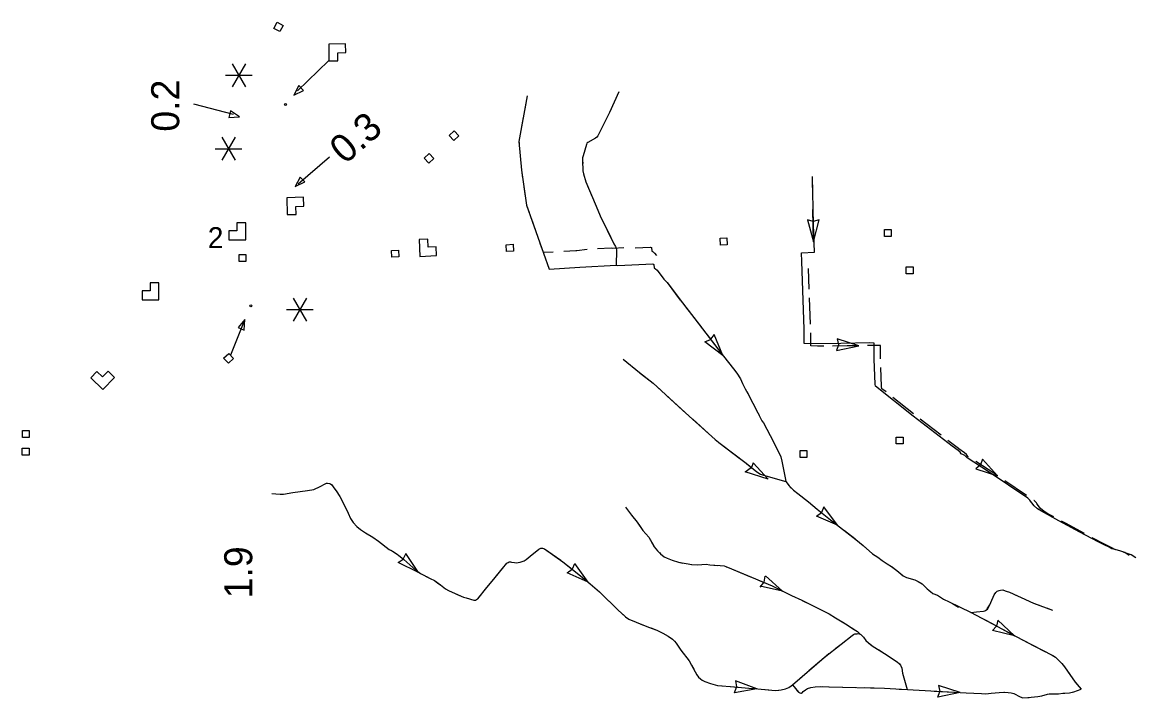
# Model space of a CAD drawing. Extents: x -160 to 6143532, y -375 to 762199.
# Drawn here: x -140.26 to -105.52, y -293.96 to -272.89 of the extents above; entities that cross this region are included whole.
import ezdxf

# ---------------------------------------------------------------- set-up
doc = ezdxf.new("R2010")
doc.units = 0
for name, color, linetype in [('Level 43', 7, 'Continuous'), ('Level 48', 7, 'Continuous'), ('Level 56', 7, 'Continuous'), ('Level 57', 7, 'Continuous'), ('Level 58', 7, 'Continuous')]:
    doc.layers.add(name, color=color, linetype=linetype)

msp = doc.modelspace()

# ---------------------------------------------------------------- linework, layer by layer
at = {"layer": 'Level 43'}
for p, q in [((-115.582, -279.105), (-115.766, -279.059)), ((-115.766, -279.059), (-115.572, -279.742)), ((-115.398, -279.053), (-115.58, -279.105)), ((-115.572, -279.742), (-115.398, -279.053)), ((-118.669, -282.632), (-118.785, -282.781)), ((-118.4, -283.288), (-118.669, -282.632)), ((-114.158, -282.98), (-114.834, -282.763)), ((-114.834, -282.763), (-114.794, -282.948)), ((-118.962, -282.854), (-118.787, -282.783)), ((-118.4, -283.288), (-118.962, -282.854)), ((-114.794, -282.95), (-114.852, -283.13)), ((-114.852, -283.13), (-114.158, -282.98)), ((-110.305, -286.514), (-110.364, -286.694)), ((-109.83, -287.042), (-110.305, -286.514)), ((-117.701, -286.915), (-117.515, -286.777)), ((-116.991, -287.138), (-117.701, -286.915)), ((-117.452, -286.635), (-117.513, -286.775)), ((-116.991, -287.138), (-117.452, -286.635)), ((-110.365, -286.696), (-110.505, -286.823)), ((-110.505, -286.823), (-109.83, -287.042)), ((-115.476, -288.298), (-115.325, -288.184)), ((-114.823, -288.576), (-115.476, -288.298)), ((-115.249, -288.008), (-115.323, -288.182)), ((-114.823, -288.576), (-115.249, -288.008)), ((-128.53, -289.742), (-128.377, -289.632)), ((-128.298, -289.458), (-128.375, -289.63)), ((-127.896, -290.05), (-128.291, -289.46)), ((-127.896, -290.05), (-128.533, -289.737)), ((-123.255, -290.065), (-123.103, -289.953)), ((-122.608, -290.352), (-123.255, -290.06)), ((-123.027, -289.777), (-123.102, -289.951)), ((-122.608, -290.352), (-123.022, -289.776)), ((-117.235, -290.51), (-117.12, -290.361)), ((-117.093, -290.171), (-117.119, -290.358)), ((-116.543, -290.629), (-117.071, -290.155)), ((-116.543, -290.629), (-117.238, -290.483)), ((-109.993, -291.862), (-109.864, -291.724)), ((-109.82, -291.537), (-109.863, -291.721)), ((-109.302, -292.022), (-109.82, -291.537)), ((-109.302, -292.022), (-109.993, -291.862)), ((-117.338, -293.679), (-118.004, -293.435)), ((-118.004, -293.435), (-117.972, -293.621)), ((-118.037, -293.801), (-117.972, -293.623)), ((-117.338, -293.679), (-118.037, -293.801)), ((-111.691, -293.94), (-111.632, -293.761)), ((-110.996, -293.795), (-111.691, -293.94)), ((-110.996, -293.795), (-111.671, -293.573)), ((-111.671, -293.573), (-111.632, -293.758))]:
    msp.add_line(p, q, dxfattribs=at)
for points in [[(-121.644, -275.063), (-121.934, -275.707), (-122.236, -276.309), (-122.302, -276.435), (-122.337, -276.477), (-122.38, -276.511), (-122.614, -276.645), (-122.642, -276.667), (-122.659, -276.708), (-122.765, -277.061), (-122.782, -277.121), (-122.778, -277.206), (-122.767, -277.528), (-122.746, -277.622), (-122.676, -277.87), (-122.354, -278.63), (-122.227, -278.933), (-121.803, -279.799), (-121.747, -279.884), (-121.732, -279.936), (-121.723, -280.005), (-121.728, -280.466)], [(-124.503, -275.192), (-124.767, -276.611), (-124.685, -277.508), (-124.525, -278.599), (-123.824, -280.59), (-122.869, -280.529), (-121.728, -280.466), (-121.675, -280.475), (-120.586, -280.432), (-120.557, -280.447), (-120.541, -280.562), (-120.499, -280.582), (-120.454, -280.623), (-120.243, -280.907), (-120.142, -281.014), (-119.665, -281.644), (-119.379, -282.005), (-118.385, -283.308), (-118.065, -283.699), (-117.963, -283.841), (-117.854, -284.016), (-117.791, -284.155), (-117.71, -284.322), (-117.627, -284.47), (-117.308, -285.075), (-117.181, -285.325), (-117.131, -285.383), (-116.928, -285.777), (-116.638, -286.35), (-116.595, -286.448), (-116.567, -286.583), (-116.468, -287.049), (-116.435, -287.219), (-116.334, -287.353), (-116.194, -287.488), (-116.064, -287.588), (-115.725, -287.847), (-115.458, -288.078), (-115.04, -288.406), (-114.253, -289.019), (-114.024, -289.213), (-113.73, -289.466), (-113.566, -289.574), (-113.436, -289.681), (-113.28, -289.781), (-113.144, -289.862), (-112.976, -289.985), (-112.775, -290.151), (-112.672, -290.204), (-112.416, -290.281), (-112.307, -290.33), (-112.185, -290.403), (-112.025, -290.557), (-111.925, -290.648), (-111.848, -290.703), (-111.702, -290.761), (-111.514, -290.879), (-111.343, -290.964), (-110.68, -291.293), (-110.321, -291.479), (-109.058, -292.152), (-108.126, -292.631), (-108.025, -292.692), (-107.936, -292.773), (-107.828, -292.885), (-107.739, -292.994), (-107.405, -293.472), (-107.228, -293.687)], [(-124.503, -275.192), (-124.578, -275.594)], [(-121.924, -275.685), (-121.934, -275.707), (-122.236, -276.309), (-122.292, -276.417)], [(-124.628, -275.863), (-124.767, -276.611), (-124.762, -276.669)], [(-122.504, -276.582), (-122.614, -276.645), (-122.642, -276.667), (-122.659, -276.708), (-122.765, -277.061), (-122.782, -277.121), (-122.778, -277.206), (-122.775, -277.302)], [(-124.737, -276.941), (-124.685, -277.508), (-124.649, -277.755)], [(-122.757, -277.574), (-122.746, -277.622), (-122.676, -277.87), (-122.477, -278.342)], [(-105.721, -289.521), (-105.865, -289.428), (-106.017, -289.377), (-106.208, -289.323), (-106.266, -289.31), (-106.348, -289.266), (-106.485, -289.196), (-106.692, -289.094), (-107.262, -288.791), (-107.917, -288.441), (-108.464, -288.142), (-108.582, -288.069), (-108.69, -287.977), (-108.767, -287.881), (-108.805, -287.827), (-108.821, -287.798), (-108.887, -287.735), (-110.122, -286.904), (-110.778, -286.474), (-110.851, -286.407), (-110.889, -286.388), (-110.962, -286.356), (-110.997, -286.299), (-111.064, -286.245), (-111.245, -286.117), (-112.464, -285.178), (-113.638, -284.245), (-113.651, -284.175), (-113.679, -283.395), (-113.686, -282.896), (-113.816, -282.892), (-114.726, -282.912), (-115.652, -282.921), (-115.862, -282.908), (-115.862, -282.459), (-115.938, -280.358), (-115.944, -280.08), (-115.543, -280.058), (-115.569, -279.198), (-115.61, -277.699)], [(-115.591, -278.408), (-115.61, -277.699)], [(-124.609, -278.025), (-124.525, -278.599), (-124.446, -278.825)], [(-122.37, -278.593), (-122.354, -278.63), (-122.227, -278.933), (-122.029, -279.338), (-121.898, -279.596)], [(-115.572, -279.742), (-115.6, -278.729)], [(-124.355, -279.082), (-124.203, -279.514)], [(-124.112, -279.782), (-124.012, -280.068), (-123.699, -280.049)], [(-123.362, -280.031), (-122.992, -280.008), (-122.954, -280.006), (-122.635, -279.971)], [(-122.313, -279.95), (-121.892, -279.927), (-121.839, -279.936), (-121.496, -279.922)], [(-121.135, -279.923), (-120.662, -279.904), (-120.633, -279.92), (-120.617, -280.035), (-120.575, -280.054), (-120.53, -280.096), (-120.477, -280.168)], [(-115.709, -281.213), (-115.732, -280.577)], [(-120.237, -280.913), (-120.142, -281.014), (-119.731, -281.556)], [(-115.669, -282.304), (-115.699, -281.485)], [(-119.563, -281.772), (-119.379, -282.005), (-119.062, -282.42)], [(-118.896, -282.637), (-118.4, -283.288)], [(-115.659, -282.985), (-115.661, -282.985), (-115.661, -282.577)], [(-115.25, -282.996), (-115.451, -282.998), (-115.659, -282.985)], [(-114.158, -282.98), (-114.525, -282.988), (-114.977, -282.993)], [(-113.48, -283.391), (-113.485, -282.972), (-113.615, -282.969), (-113.885, -282.975)], [(-121.509, -283.401), (-121.002, -283.818), (-120.573, -284.153), (-120.312, -284.389), (-119.454, -285.172), (-118.64, -285.909), (-118.485, -286.032), (-117.679, -286.645), (-117.337, -286.918), (-117.23, -286.986), (-117.133, -287.018), (-116.943, -287.066), (-116.554, -287.186), (-116.435, -287.219)], [(-118.228, -283.5), (-118.065, -283.699), (-117.976, -283.823)], [(-117.976, -283.823), (-117.963, -283.841), (-117.854, -284.016), (-117.791, -284.155), (-117.778, -284.181)], [(-113.312, -284.421), (-113.437, -284.322), (-113.45, -284.252), (-113.471, -283.664)], [(-120.981, -283.834), (-120.573, -284.153), (-120.35, -284.355)], [(-117.654, -284.423), (-117.627, -284.47), (-117.308, -285.075), (-117.271, -285.148)], [(-120.148, -284.539), (-119.543, -285.091)], [(-112.457, -285.101), (-113.098, -284.591)], [(-119.34, -285.274), (-118.733, -285.824)], [(-117.132, -285.381), (-117.131, -285.383), (-116.928, -285.777), (-116.759, -286.11)], [(-111.594, -285.77), (-112.243, -285.27)], [(-118.525, -286), (-118.485, -286.032), (-117.873, -286.497)], [(-111.054, -286.187), (-111.378, -285.937)], [(-110.74, -286.442), (-110.761, -286.433), (-110.796, -286.375), (-110.863, -286.321), (-111.044, -286.194), (-111.054, -286.187)], [(-116.636, -286.354), (-116.595, -286.448), (-116.567, -286.583), (-116.468, -287.049), (-116.449, -287.149)], [(-109.83, -287.042), (-109.921, -286.98), (-110.514, -286.591)], [(-117.656, -286.663), (-117.337, -286.918), (-117.23, -286.986), (-117.2, -286.996)], [(-132.471, -287.589), (-132.349, -287.599), (-132.212, -287.614), (-132.113, -287.609), (-131.817, -287.56), (-131.362, -287.499), (-131.161, -287.465), (-130.971, -287.371), (-130.809, -287.283), (-130.77, -287.27), (-130.733, -287.27), (-130.679, -287.272), (-130.644, -287.285), (-130.603, -287.32), (-130.541, -287.417), (-130.465, -287.503), (-130.35, -287.681), (-130.157, -288.066), (-130.09, -288.198), (-130.015, -288.369), (-129.935, -288.494), (-129.822, -288.616), (-129.708, -288.713), (-129.554, -288.815), (-129.325, -288.949), (-129.141, -289.079), (-128.808, -289.33), (-128.706, -289.388), (-128.561, -289.479), (-128.36, -289.644), (-127.982, -289.975), (-127.831, -290.079), (-127.53, -290.243), (-127.402, -290.306), (-127.216, -290.44), (-127.052, -290.563), (-126.939, -290.623), (-126.495, -290.819), (-126.413, -290.843), (-126.175, -290.917), (-126.143, -290.919), (-126.117, -290.915), (-126.089, -290.899), (-126.052, -290.869), (-125.764, -290.519), (-125.55, -290.255), (-125.139, -289.759), (-125.098, -289.735), (-125.066, -289.722), (-125.027, -289.722), (-124.992, -289.727), (-124.907, -289.744), (-124.856, -289.746), (-124.791, -289.74), (-124.724, -289.729), (-124.663, -289.709), (-124.598, -289.686), (-124.535, -289.647), (-124.419, -289.547), (-124.146, -289.327), (-124.079, -289.294), (-124.047, -289.29), (-124.025, -289.296), (-123.995, -289.303), (-123.967, -289.314), (-123.394, -289.72), (-122.898, -290.114), (-122.544, -290.404), (-122.254, -290.658), (-121.666, -291.222), (-121.44, -291.431), (-121.336, -291.509), (-121.109, -291.598), (-120.724, -291.753), (-120.467, -291.851), (-120.279, -291.942), (-120.106, -292.039), (-119.976, -292.131), (-119.909, -292.189), (-119.857, -292.254), (-119.712, -292.475), (-119.457, -292.81), (-119.377, -292.94), (-119.215, -293.241), (-119.157, -293.312), (-119.1, -293.368), (-119.044, -293.407), (-118.96, -293.45), (-118.791, -293.517), (-118.568, -293.572), (-118.43, -293.587), (-118.177, -293.604), (-117.595, -293.656), (-117.429, -293.669), (-116.871, -293.721), (-116.752, -293.73), (-116.67, -293.725), (-116.585, -293.708), (-116.447, -293.678), (-116.347, -293.639), (-116.233, -293.559)], [(-108.924, -287.651), (-109.603, -287.194)], [(-116.31, -287.377), (-116.194, -287.488), (-116.064, -287.588), (-115.725, -287.847), (-115.673, -287.891)], [(-108.078, -288.32), (-108.263, -288.219), (-108.381, -288.145), (-108.489, -288.053), (-108.566, -287.958), (-108.604, -287.903), (-108.62, -287.875), (-108.687, -287.811), (-108.697, -287.804)], [(-130.133, -288.113), (-130.09, -288.198), (-130.015, -288.369), (-129.935, -288.494), (-129.822, -288.616), (-129.708, -288.713), (-129.647, -288.753)], [(-121.44, -288.012), (-121.248, -288.265), (-121.074, -288.486), (-120.902, -288.74), (-120.713, -288.955), (-120.541, -289.253), (-120.445, -289.373), (-120.346, -289.469), (-120.233, -289.562), (-120.139, -289.609), (-119.982, -289.667), (-119.787, -289.731), (-119.37, -289.807), (-119.196, -289.813), (-118.928, -289.792), (-118.809, -289.818), (-118.485, -289.836), (-118.363, -289.845), (-118.256, -289.888), (-117.507, -290.197), (-116.867, -290.465), (-116.259, -290.774), (-115.942, -290.913), (-115.627, -291.071), (-115.083, -291.344), (-114.891, -291.464), (-114.573, -291.653), (-114.301, -291.825), (-114.197, -291.895), (-114.013, -292.071), (-113.937, -292.176), (-113.862, -292.248), (-113.742, -292.336), (-113.358, -292.577), (-112.962, -292.839), (-112.888, -292.897), (-112.856, -292.946), (-112.822, -293.033), (-112.795, -293.188), (-112.656, -293.702)], [(-115.467, -288.07), (-115.458, -288.078), (-115.04, -288.406), (-114.822, -288.575)], [(-121.027, -288.555), (-120.902, -288.74), (-120.713, -288.955), (-120.559, -289.223)], [(-107.116, -288.838), (-107.716, -288.518), (-107.838, -288.451)], [(-129.415, -288.896), (-129.325, -288.949), (-129.141, -289.079), (-128.808, -289.33), (-128.745, -289.366)], [(-114.607, -288.743), (-114.284, -288.995)], [(-114.284, -288.995), (-114.253, -289.019), (-114.024, -289.213), (-113.97, -289.259)], [(-106.148, -289.342), (-106.284, -289.272), (-106.491, -289.17), (-106.875, -288.966)], [(-124.153, -289.332), (-124.146, -289.327), (-124.079, -289.294), (-124.047, -289.29), (-124.025, -289.296), (-123.995, -289.303), (-123.967, -289.314), (-123.462, -289.672)], [(-128.517, -289.516), (-128.36, -289.644), (-127.982, -289.975), (-127.888, -290.039)], [(-125.107, -289.74), (-125.098, -289.735), (-125.066, -289.722), (-125.027, -289.722), (-124.992, -289.727), (-124.907, -289.744), (-124.856, -289.746), (-124.791, -289.74), (-124.724, -289.729), (-124.663, -289.709), (-124.598, -289.686), (-124.535, -289.647), (-124.419, -289.547), (-124.365, -289.504)], [(-120.384, -289.432), (-120.346, -289.469), (-120.233, -289.562), (-120.139, -289.609), (-119.982, -289.667), (-119.787, -289.731), (-119.647, -289.756)], [(-113.763, -289.437), (-113.73, -289.466), (-113.566, -289.574), (-113.436, -289.681), (-113.28, -289.781), (-113.144, -289.862), (-113.09, -289.901)], [(-105.521, -289.597), (-105.664, -289.505), (-105.816, -289.454), (-105.892, -289.433)], [(-125.81, -290.574), (-125.764, -290.519), (-125.55, -290.255), (-125.29, -289.941)], [(-123.245, -289.838), (-122.898, -290.114), (-122.608, -290.352)], [(-119.379, -289.805), (-119.37, -289.807), (-119.196, -289.813), (-118.928, -289.792), (-118.809, -289.818), (-118.564, -289.832)], [(-118.297, -289.872), (-118.256, -289.888), (-117.539, -290.184)], [(-112.875, -290.069), (-112.775, -290.151), (-112.672, -290.204), (-112.416, -290.281), (-112.307, -290.33), (-112.185, -290.403), (-112.153, -290.434)], [(-127.652, -290.176), (-127.53, -290.243), (-127.402, -290.306), (-127.298, -290.381)], [(-127.298, -290.381), (-127.216, -290.44), (-127.052, -290.563), (-126.961, -290.611)], [(-117.287, -290.289), (-116.867, -290.465), (-116.543, -290.629)], [(-126.712, -290.723), (-126.495, -290.819), (-126.413, -290.843), (-126.175, -290.917), (-126.143, -290.919), (-126.117, -290.915), (-126.089, -290.899), (-126.052, -290.869), (-125.983, -290.785)], [(-122.4, -290.53), (-122.254, -290.658), (-122.099, -290.807)], [(-116.299, -290.753), (-116.259, -290.774), (-115.942, -290.913), (-115.926, -290.921)], [(-111.954, -290.622), (-111.925, -290.648), (-111.848, -290.703), (-111.702, -290.761), (-111.514, -290.879), (-111.343, -290.964), (-111.24, -291.015), (-111.054, -291.132)], [(-110.662, -291.303), (-110.491, -291.282), (-110.268, -291.253), (-110.224, -291.244), (-110.195, -291.225), (-110.147, -291.193), (-110.112, -291.142), (-110.081, -291.078), (-109.934, -290.744), (-109.89, -290.674), (-109.842, -290.639), (-109.785, -290.61), (-109.74, -290.601), (-109.667, -290.595), (-109.594, -290.62), (-109.463, -290.665), (-109.094, -290.833), (-108.712, -291.008), (-108.12, -291.225)], [(-110.152, -291.186), (-110.074, -291.064), (-109.934, -290.744), (-109.89, -290.674), (-109.842, -290.639), (-109.785, -290.61), (-109.74, -290.601), (-109.667, -290.595), (-109.594, -290.62), (-109.53, -290.642)], [(-109.279, -290.749), (-109.094, -290.833), (-108.712, -291.008), (-108.529, -291.075)], [(-122.099, -290.807), (-121.803, -291.09)], [(-115.926, -290.921), (-115.627, -291.071), (-115.56, -291.105)], [(-121.605, -291.278), (-121.44, -291.431), (-121.336, -291.509), (-121.109, -291.598), (-120.905, -291.68)], [(-115.316, -291.227), (-115.083, -291.344), (-114.891, -291.464), (-114.606, -291.634)], [(-108.272, -291.169), (-108.12, -291.225)], [(-120.651, -291.781), (-120.467, -291.851), (-120.279, -291.942), (-120.106, -292.039), (-119.976, -292.131), (-119.934, -292.168)], [(-114.374, -291.779), (-114.301, -291.825), (-114.197, -291.895), (-114.013, -292.071), (-113.937, -292.176), (-113.862, -292.248), (-113.766, -292.318)], [(-110.221, -291.526), (-110.024, -291.637), (-109.302, -292.022)], [(-116.233, -293.559), (-115.244, -292.702), (-114.715, -292.286), (-114.365, -292.014), (-114.323, -291.985), (-114.285, -291.969), (-114.233, -291.961), (-114.193, -291.959), (-114.151, -291.964), (-114.114, -291.974)], [(-114.877, -292.414), (-114.715, -292.286), (-114.365, -292.014), (-114.323, -291.985), (-114.285, -291.969), (-114.233, -291.961), (-114.209, -291.96)], [(-109.061, -292.151), (-109.058, -292.152), (-108.696, -292.338)], [(-119.771, -292.385), (-119.712, -292.475), (-119.457, -292.81), (-119.377, -292.94), (-119.311, -293.062)], [(-113.536, -292.465), (-113.358, -292.577), (-112.962, -292.839), (-112.888, -292.897), (-112.866, -292.931)], [(-108.696, -292.338), (-108.332, -292.525)], [(-115.717, -293.112), (-115.244, -292.702), (-115.092, -292.583)], [(-108.09, -292.652), (-108.025, -292.692), (-107.936, -292.773), (-107.828, -292.885), (-107.739, -292.994), (-107.553, -293.261)], [(-112.794, -293.192), (-112.656, -293.702)], [(-119.171, -293.295), (-119.157, -293.312), (-119.1, -293.368), (-119.044, -293.407), (-118.96, -293.45), (-118.791, -293.517), (-118.568, -293.572), (-118.43, -293.587), (-118.426, -293.587)], [(-116.233, -293.559), (-115.923, -293.291)], [(-107.396, -293.484), (-107.228, -293.687)], [(-118.154, -293.606), (-117.595, -293.656), (-117.429, -293.669), (-117.338, -293.677)], [(-117.066, -293.703), (-116.871, -293.721), (-116.752, -293.73), (-116.67, -293.725), (-116.658, -293.723)], [(-116.658, -293.723), (-116.585, -293.708), (-116.447, -293.678), (-116.347, -293.639), (-116.276, -293.589)], [(-116.233, -293.559), (-116.042, -293.786), (-116.004, -293.805), (-115.973, -293.812), (-115.947, -293.812), (-115.93, -293.801), (-115.898, -293.76), (-115.826, -293.706), (-115.761, -293.673), (-115.658, -293.643), (-115.519, -293.619), (-115.301, -293.608), (-115.1, -293.613), (-113.363, -293.656), (-112.825, -293.693), (-110.811, -293.805), (-110.335, -293.825), (-110.193, -293.833), (-110.035, -293.812), (-109.782, -293.797), (-109.617, -293.786), (-109.496, -293.79), (-109.408, -293.801), (-109.326, -293.827), (-109.127, -293.931), (-109.044, -293.957), (-108.89, -293.95), (-108.572, -293.92), (-108.453, -293.894), (-108.276, -293.842), (-108.224, -293.833), (-108.176, -293.833), (-108.074, -293.84), (-108.001, -293.84), (-107.925, -293.836), (-107.793, -293.814), (-107.728, -293.81), (-107.586, -293.803), (-107.456, -293.768), (-107.228, -293.687)], [(-116.091, -293.728), (-116.042, -293.786), (-116.004, -293.805), (-115.973, -293.812), (-115.947, -293.812), (-115.93, -293.801), (-115.898, -293.76), (-115.826, -293.706), (-115.761, -293.673), (-115.658, -293.643), (-115.519, -293.619), (-115.36, -293.611)], [(-115.087, -293.613), (-114.268, -293.633)], [(-113.995, -293.64), (-113.363, -293.656), (-113.177, -293.669)], [(-112.904, -293.687), (-112.825, -293.693), (-112.087, -293.734)], [(-111.814, -293.749), (-110.996, -293.795)], [(-109.634, -293.787), (-109.617, -293.786), (-109.496, -293.79), (-109.408, -293.801), (-109.326, -293.827), (-109.127, -293.931), (-109.044, -293.957), (-108.89, -293.95), (-108.85, -293.946)], [(-108.578, -293.92), (-108.572, -293.92), (-108.453, -293.894), (-108.276, -293.842), (-108.224, -293.833), (-108.176, -293.833), (-108.074, -293.84), (-108.001, -293.84), (-107.925, -293.836), (-107.793, -293.814), (-107.772, -293.812)], [(-107.502, -293.781), (-107.456, -293.768), (-107.228, -293.687)]]:
    msp.add_lwpolyline(points, dxfattribs=at)
at = {"layer": 'Level 48'}
for p, q in [((-133.297, -274.187), (-133.711, -274.903)), ((-133.711, -274.187), (-133.297, -274.903)), ((-133.918, -274.545), (-133.091, -274.545)), ((-133.618, -276.48), (-134.032, -277.197)), ((-134.032, -276.48), (-133.618, -277.197)), ((-134.239, -276.839), (-133.411, -276.839)), ((-131.391, -281.495), (-131.805, -282.211)), ((-131.805, -281.495), (-131.391, -282.211)), ((-132.012, -281.853), (-131.185, -281.853))]:
    msp.add_line(p, q, dxfattribs=at)
msp.add_lwpolyline([(-133.675, -275.775), (-134.911, -275.449)], dxfattribs=at)
msp.add_lwpolyline([(-133.759, -275.657), (-133.813, -275.861), (-133.48, -275.84)], close=True, dxfattribs=at)
at = {"layer": 'Level 56'}
for points in [[(-132.226, -273.187), (-132.415, -273.084), (-132.312, -272.895), (-132.123, -272.998)], [(-131.487, -275.017), (-131.635, -274.866), (-131.788, -275.163)], [(-126.784, -276.281), (-126.638, -276.439), (-126.797, -276.586), (-126.943, -276.427)], [(-127.568, -276.984), (-127.422, -277.142), (-127.58, -277.289), (-127.726, -277.131)], [(-131.447, -277.874), (-131.594, -277.722), (-131.747, -278.019)], [(-118.274, -279.618), (-118.263, -279.833), (-118.478, -279.845), (-118.49, -279.63)], [(-113.363, -279.571), (-113.363, -279.355), (-113.147, -279.355), (-113.147, -279.571)], [(-128.523, -279.998), (-128.511, -280.213), (-128.727, -280.224), (-128.738, -280.009)], [(-124.948, -279.818), (-124.936, -280.033), (-125.152, -280.045), (-125.163, -279.83)], [(-133.498, -280.354), (-133.498, -280.139), (-133.282, -280.139), (-133.282, -280.354)], [(-112.685, -280.737), (-112.685, -280.522), (-112.469, -280.522), (-112.469, -280.737)], [(-133.977, -283.372), (-133.82, -283.224), (-133.672, -283.382), (-133.829, -283.529)], [(-140.258, -285.845), (-140.258, -285.629), (-140.042, -285.629), (-140.042, -285.845)], [(-112.996, -286.042), (-112.996, -285.827), (-112.78, -285.827), (-112.78, -286.042)], [(-140.26, -286.394), (-140.26, -286.178), (-140.044, -286.178), (-140.044, -286.394)], [(-115.993, -286.466), (-115.993, -286.251), (-115.777, -286.251), (-115.777, -286.466)]]:
    msp.add_lwpolyline(points, close=True, dxfattribs=at)
msp.add_lwpolyline([(-133.344, -282.231), (-133.764, -283.274)], dxfattribs=at)
msp.add_circle((-133.129, -281.739), 0.031, dxfattribs=at)
at = {"layer": 'Level 57'}
msp.add_lwpolyline([(-133.529, -282.413), (-133.334, -282.492), (-133.313, -282.159)], close=True, dxfattribs=at)
at = {"layer": 'Level 58'}
for points in [[(-130.7, -273.572), (-130.691, -274.097), (-130.414, -274.093), (-130.418, -273.844), (-130.17, -273.84), (-130.175, -273.563)], [(-132.007, -278.367), (-131.992, -278.892), (-131.715, -278.885), (-131.722, -278.636), (-131.474, -278.629), (-131.481, -278.353)], [(-133.285, -279.679), (-133.285, -279.153), (-133.563, -279.153), (-133.563, -279.402), (-133.811, -279.402), (-133.811, -279.679)], [(-127.857, -280.194), (-127.332, -280.17), (-127.344, -279.893), (-127.593, -279.904), (-127.604, -279.656), (-127.88, -279.669)], [(-135.998, -281.545), (-135.998, -281.02), (-136.275, -281.02), (-136.275, -281.268), (-136.523, -281.268), (-136.523, -281.545)], [(-137.749, -284.345), (-137.383, -283.968), (-137.581, -283.775), (-137.755, -283.953), (-137.933, -283.78), (-138.126, -283.978)]]:
    msp.add_lwpolyline(points, close=True, dxfattribs=at)
for points in [[(-131.671, -275.032), (-130.708, -274.095)], [(-131.657, -277.935), (-130.677, -277.089)]]:
    msp.add_lwpolyline(points, dxfattribs=at)
msp.add_circle((-132.048, -275.462), 0.031, dxfattribs=at)

# ---------------------------------------------------------------- texts
at = {"layer": 'Level 48'}
for s, rotation, p in [('0.2', 90, (-135.363, -276.306)), ('0.3', 41.1138, (-130.19, -277.349)), ('1.9', 90, (-133.085, -290.86))]:
    msp.add_text(s, height=0.8737, rotation=rotation, dxfattribs=at).set_placement(p)
at = {"layer": 'Level 58'}
msp.add_text('2', height=0.655, dxfattribs=at).set_placement((-134.472, -279.938))

doc.saveas('drawing.dxf')
